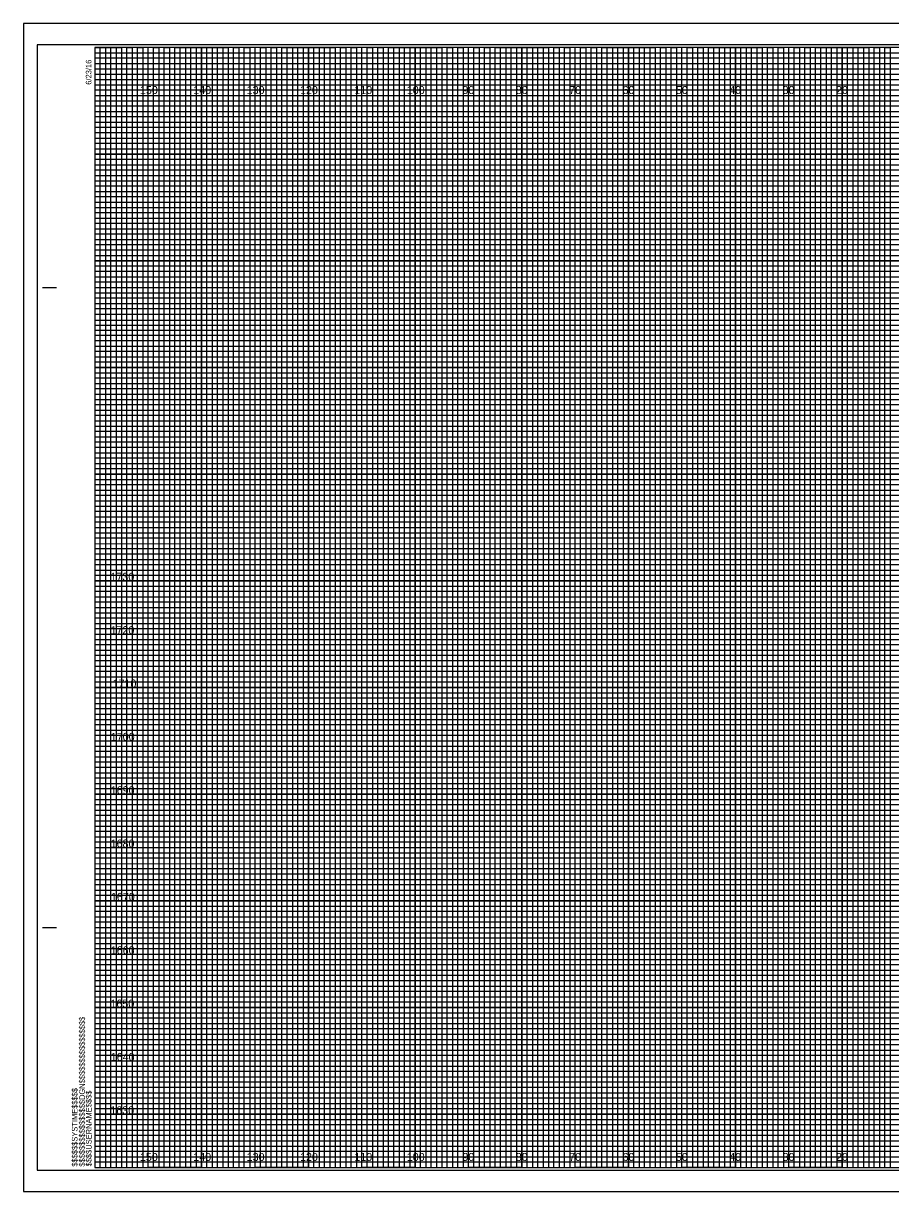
# Model space of a CAD drawing. Extents: x -13 to 323, y -5 to 6154.
# Drawn here: x -13.4 to 149.1, y 1315.5 to 1534.5 of the extents above; entities that cross this region are included whole.
import ezdxf

# ---------------------------------------------------------------- set-up
doc = ezdxf.new("R2010")
doc.units = 0
for name, color, linetype in [('Prop Retaining Wall', 7, 'Continuous'), ('Prop XS Alignment Label', 7, 'Continuous'), ('Prop XS DDE', 7, 'Continuous'), ('Prop XS DDE Elevations', 7, 'Continuous'), ('Prop XS DDE Slope Text', 7, 'Continuous'), ('Prop XS Earthwork Shape', 7, 'Continuous'), ('Prop XS Elevation Labels', 7, 'Continuous'), ('Prop XS Station Labels', 7, 'Continuous'), ('Raster_Level_0', 7, 'Continuous'), ('Scratch_Level_3', 7, 'Continuous'), ('Sheet Cutting Line CELL', 7, 'Continuous')]:
    doc.layers.add(name, color=color, linetype=linetype)

msp = doc.modelspace()

# ---------------------------------------------------------------- linework, layer by layer
at = {"layer": 'Prop Retaining Wall'}
for p, q in [((0, 1529), (260, 1529)), ((260, 1527.98), (0, 1527.98)), ((0, 1527.98), (0, 1527)), ((0, 1527), (260, 1527)), ((260, 1525.89), (0, 1525.89)), ((0, 1525.89), (0, 1524)), ((0, 1524), (320, 1524))]:
    msp.add_line(p, q, dxfattribs=at)
for points in [[(0, 1523), (270, 1523), (320, 1523), (320, 1522), (0, 1522)], [(0, 1521), (320, 1521), (320, 1519), (0, 1519)], [(0, 1518), (320, 1518), (320, 1517), (0, 1516.98)], [(0, 1516), (320, 1516), (320, 1514), (0, 1514)], [(0, 1513), (320, 1513), (320, 1512), (0, 1512)], [(0, 1511), (320, 1511), (320, 1509), (0, 1509)], [(0, 1508), (320, 1508), (320, 1507), (0, 1507)], [(0, 1506), (320, 1506), (320, 1504), (0, 1504)], [(0, 1503), (320, 1503), (320, 1502), (0, 1502)], [(0, 1501), (320, 1501), (320, 1499), (0, 1499)], [(0, 1498), (320, 1498), (320, 1497), (0, 1497)], [(0, 1496), (320, 1496), (320, 1493.95), (320, 1493), (320, 1492), (0, 1492)], [(0, 1494), (320, 1494), (320, 1493), (0, 1493)], [(0, 1491), (320, 1491), (320, 1489), (0, 1489.03)], [(0, 1489.03), (320, 1489), (320, 1488), (0, 1488)], [(0, 1487), (320, 1487), (320, 1486), (0, 1486)], [(0, 1484), (320, 1484), (320, 1483), (0, 1483)], [(0, 1482), (320, 1482), (320, 1481), (0, 1481)], [(-0.07, 1478.89), (320, 1478.89), (320, 1477.88), (-0.07, 1477.88)], [(0, 1477), (320, 1477), (320, 1476), (0, 1476)], [(0, 1474), (320, 1474), (320, 1473), (0, 1473)], [(0, 1472), (320, 1472), (320, 1471), (0, 1471)], [(0, 1469), (320, 1469), (320, 1468), (0, 1468)], [(0, 1467), (320, 1467), (320, 1466), (0, 1466)], [(0, 1464), (320, 1464), (320, 1463), (0, 1463)], [(0, 1462), (320, 1462), (320, 1461), (0, 1461)], [(0, 1459), (320, 1459), (319.99, 1457.98), (0, 1458)], [(0, 1457), (320, 1457), (320, 1456), (0, 1456)], [(0, 1454), (320, 1454), (320, 1453), (0, 1453)], [(0, 1452), (320, 1452), (320, 1451), (0, 1451)], [(0, 1449), (320, 1449), (320, 1448), (0, 1448)], [(0, 1447), (320, 1447), (320, 1446), (0, 1446)], [(0, 1444), (320, 1444), (320, 1443), (0, 1443)], [(0, 1442), (320, 1442), (320, 1441), (0, 1441)], [(0, 1439), (320, 1439), (320, 1438), (0, 1438)], [(0, 1436.99), (320.07, 1436.91), (320, 1436), (0, 1436)], [(0, 1434), (320, 1434), (320, 1433), (0, 1433)], [(0, 1432), (320, 1432), (320, 1431), (0, 1431)], [(0, 1429), (320, 1429), (320, 1428), (0, 1428)], [(0, 1427), (320, 1427), (320, 1426), (0, 1426)], [(0, 1424), (320, 1424), (320, 1423), (0, 1423)], [(0, 1422), (320, 1422), (320, 1421), (0, 1421)], [(0, 1419), (320, 1419), (320, 1418), (0, 1418)], [(0, 1417), (320, 1417), (320, 1416), (0, 1416)], [(0, 1414), (320, 1414), (320, 1413), (0, 1413)], [(0, 1412), (320, 1412), (320, 1411), (0, 1411)], [(0, 1409), (320, 1409), (320, 1408), (0, 1408)], [(0, 1407), (320, 1407), (320, 1406), (0, 1406)], [(0, 1404), (320, 1404), (320, 1403), (0, 1403)], [(0, 1402), (320, 1402), (320, 1401), (0, 1401)], [(0, 1399), (320, 1399), (319.99, 1397.98), (0, 1398)], [(0, 1397), (320, 1397), (320, 1396), (0, 1396)], [(0, 1394), (320, 1394), (320, 1393), (0, 1393)], [(0, 1392), (320, 1392), (320, 1391), (0, 1391)], [(0, 1389), (320, 1389), (320, 1388), (0, 1388)], [(0, 1387), (320, 1387), (320, 1386), (0, 1386)], [(0, 1384), (320, 1384), (320, 1383), (0, 1383)], [(0, 1382), (320, 1382), (320, 1381), (0, 1381)], [(0, 1379), (320, 1379), (320, 1378), (0, 1378)], [(0, 1376.99), (320.07, 1376.91), (320, 1376), (0, 1376)], [(0, 1374), (320, 1374), (320, 1373), (0, 1373)], [(0, 1372), (320, 1372), (320, 1371), (0, 1371)], [(0, 1369), (320, 1369), (320, 1368), (0, 1368)], [(0, 1367), (320, 1367), (320, 1366), (0, 1366)], [(0, 1364), (320, 1364), (320, 1363), (0, 1363)], [(0, 1362), (320, 1362), (320, 1361), (0, 1361)], [(0, 1359), (320, 1359), (320, 1358), (0, 1358)], [(0, 1357), (320, 1357), (320, 1356), (0, 1356)], [(0, 1354), (320, 1354), (320, 1353), (0, 1353)], [(0, 1352), (320, 1352), (320, 1351), (0, 1351)], [(0, 1349), (320, 1349), (320, 1348), (0, 1348)], [(0, 1347), (320, 1347), (320, 1346), (0, 1346)], [(0, 1344), (320, 1344), (320, 1343), (0, 1343)], [(0, 1342), (320, 1342), (320, 1341), (0, 1341)], [(0, 1339), (320, 1339), (320, 1338), (0, 1338)], [(0, 1337), (320, 1337), (320, 1336), (0, 1336)], [(0, 1334), (320, 1334), (320, 1333), (0, 1333)], [(0, 1332), (320, 1332), (320, 1331), (0, 1331)], [(0, 1329), (320, 1329), (320, 1328), (0, 1328)], [(0, 1327), (320, 1327), (320, 1326), (0, 1326)], [(0, 1324), (320, 1324), (320, 1323), (0, 1323)], [(0, 1322), (320, 1322), (320, 1321), (0, 1321)]]:
    msp.add_lwpolyline(points, dxfattribs=at)
at = {"layer": 'Prop XS Alignment Label'}
for p, q in [((-9.8, 1485), (-7.3, 1485)), ((-9.7, 1485), (-7.2, 1485)), ((-9.8, 1365), (-7.3, 1365)), ((-9.7, 1365), (-7.2, 1365)), ((0, 1320), (0, 1320)), ((0, 1320), (0, 1320)), ((0, 1320), (0, 1320)), ((0, 1320), (0, 1320)), ((0, 1320), (0, 1320)), ((0, 1320), (0, 1320)), ((0, 1320), (0, 1320))]:
    msp.add_line(p, q, dxfattribs=at)
msp.add_lwpolyline([(320, 1530), (0, 1530), (0, 1320), (320, 1320)], close=True, dxfattribs=at)
at = {"layer": 'Prop XS DDE'}
msp.add_lwpolyline([(-13.4, 1315.5), (323.3, 1315.5), (323.3, 1534.5), (-13.4, 1534.5)], close=True, dxfattribs=at)
at = {"layer": 'Prop XS DDE Elevations'}
for p, q in [((10, 1320), (10, 1530)), ((20, 1320), (20, 1530)), ((30, 1320), (30, 1530)), ((40, 1320), (40, 1530)), ((50, 1320), (50, 1530)), ((60, 1320), (60, 1530)), ((70, 1320), (70, 1530)), ((80, 1320), (80, 1530)), ((90, 1320), (90, 1530)), ((100, 1320), (100, 1530)), ((110, 1320), (110, 1530)), ((120, 1320), (120, 1530)), ((130, 1320), (130, 1530)), ((140, 1320), (140, 1530)), ((0, 1520), (320, 1520)), ((0, 1510), (320, 1510)), ((0, 1500), (320, 1500)), ((0, 1490), (320, 1490)), ((0, 1480), (320, 1480)), ((0, 1470), (320, 1470)), ((0, 1460), (320, 1460)), ((0, 1450), (320, 1450)), ((0, 1440), (320, 1440)), ((0, 1430), (320, 1430)), ((0, 1420), (320, 1420)), ((0, 1410), (320, 1410)), ((0, 1400), (320, 1400)), ((0, 1390), (320, 1390)), ((0, 1380), (320, 1380)), ((0, 1370), (320, 1370)), ((0, 1360), (320, 1360)), ((0, 1350), (320, 1350)), ((0, 1340), (320, 1340)), ((0, 1330), (320, 1330))]:
    msp.add_line(p, q, dxfattribs=at)
at = {"layer": 'Prop XS DDE Slope Text'}
msp.add_lwpolyline([(-10.8, 1319.5), (322.4, 1319.5), (322.4, 1530.5), (-10.8, 1530.5)], close=True, dxfattribs=at)
at = {"layer": 'Prop XS Earthwork Shape'}
for p, q in [((10, 1530), (0, 1530)), ((10, 1320), (10, 1530)), ((30, 1530), (20, 1530)), ((20, 1530), (20, 1320)), ((30, 1320), (30, 1530)), ((50, 1530), (40, 1530)), ((40, 1530), (40, 1320)), ((50, 1320), (50, 1530)), ((70, 1530), (60, 1530)), ((60, 1530), (60, 1320)), ((70, 1320), (70, 1530)), ((90, 1530), (80, 1530)), ((80, 1530), (80, 1320)), ((90, 1320), (90, 1530)), ((110, 1530), (100, 1530)), ((100, 1530), (100, 1320)), ((110, 1320), (110, 1530)), ((130, 1530), (120, 1530)), ((120, 1530), (120, 1320)), ((130, 1320), (130, 1530)), ((150, 1530), (140, 1530)), ((140, 1530), (140, 1320)), ((20, 1320), (10, 1320)), ((40, 1320), (30, 1320)), ((60, 1320), (50, 1320)), ((80, 1320), (70, 1320)), ((100, 1320), (90, 1320)), ((120, 1320), (110, 1320)), ((140, 1320), (130, 1320))]:
    msp.add_line(p, q, dxfattribs=at)
for points in [[(0, 1520), (320, 1520), (320, 1510), (0, 1510)], [(0, 1500), (320, 1500), (320, 1490), (0, 1490)], [(0, 1480), (320, 1480), (320, 1470), (0, 1470)], [(0, 1460), (320, 1460), (320, 1450), (0, 1450)], [(0, 1440), (320, 1440), (320, 1430), (0, 1430)], [(0, 1420), (320, 1420), (320, 1410), (0, 1410)], [(0, 1400), (320, 1400), (320, 1390), (0, 1390)], [(0, 1380), (320, 1380), (320, 1370), (0, 1370)], [(0, 1360), (320, 1360), (320, 1350), (0, 1350)], [(0, 1340), (320, 1340), (320, 1330), (0, 1330)]]:
    msp.add_lwpolyline(points, dxfattribs=at)
at = {"layer": 'Prop XS Elevation Labels'}
for points in [[(0, 1320), (1, 1320), (1, 1530), (2, 1530), (2, 1320)], [(2, 1320), (3, 1320), (3, 1530), (4, 1530), (4, 1320)], [(5, 1320), (6, 1320), (6, 1530), (7, 1530), (7, 1320)], [(7, 1320), (8, 1320), (8, 1530), (9, 1530), (9, 1320)], [(10, 1320), (11, 1320), (11, 1530), (12, 1530), (12, 1320)], [(12, 1320), (13, 1320), (13, 1530), (14, 1530), (14, 1320)], [(15, 1320), (16, 1320), (16, 1530), (17, 1530), (17, 1320)], [(17, 1320), (18, 1320), (18, 1530), (19, 1530), (19, 1320)], [(20, 1320), (21, 1320), (21, 1530), (22, 1530), (22, 1320)], [(22, 1320), (23, 1320), (23, 1530), (24, 1530), (24, 1320)], [(25, 1320), (26, 1320), (26, 1530), (27, 1530), (27, 1320)], [(27, 1320), (28, 1320), (28, 1530), (29, 1530), (29, 1320)], [(30, 1320), (31, 1320), (31, 1530), (32, 1530), (32, 1320)], [(32, 1320), (33, 1320), (33, 1530), (34, 1530), (34, 1320)], [(35, 1320), (36, 1320), (36, 1530), (37, 1530), (37, 1320)], [(37, 1320), (38, 1320), (38, 1530), (39, 1530), (39, 1320)], [(40, 1320), (41, 1320), (41, 1530), (42, 1530), (42, 1320)], [(42, 1320), (43, 1320), (43, 1530), (44, 1530), (44, 1320)], [(45, 1320), (46, 1320), (46, 1530), (47, 1530), (47, 1320)], [(47, 1320), (48, 1320), (48, 1530), (49, 1530), (49, 1320)], [(50, 1320), (51, 1320), (51, 1530), (52, 1530), (52, 1320)], [(52, 1320), (53, 1320), (53, 1530), (54, 1530), (54, 1320)], [(55, 1320), (56, 1320), (56, 1530), (57, 1530), (57, 1320)], [(57, 1320), (58, 1320), (58, 1530), (59, 1530), (59, 1320)], [(60, 1320), (61, 1320), (61, 1530), (62, 1530), (62, 1320)], [(62, 1320), (63, 1320), (63, 1530), (64, 1530), (64, 1320)], [(65, 1320), (66, 1320), (66, 1530), (67, 1530), (67, 1320)], [(67, 1320), (68, 1320), (68, 1530), (69, 1530), (69, 1320)], [(70, 1320), (71, 1320), (71, 1530), (72, 1530), (72, 1320)], [(72, 1320), (73, 1320), (73, 1530), (74, 1530), (74, 1320)], [(75, 1320), (76, 1320), (76, 1530), (77, 1530), (77, 1320)], [(77, 1320), (78, 1320), (78, 1530), (79, 1530), (79, 1320)], [(80, 1320), (81, 1320), (81, 1530), (82, 1530), (82, 1320)], [(82, 1320), (83, 1320), (83, 1530), (84, 1530), (84, 1320)], [(85, 1320), (86, 1320), (86, 1530), (87, 1530), (87, 1320)], [(87, 1320), (88, 1320), (88, 1530), (89, 1530), (89, 1320)], [(90, 1320), (91, 1320), (91, 1530), (92, 1530), (92, 1320)], [(92, 1320), (93, 1320), (93, 1530), (94, 1530), (94, 1320)], [(95, 1320), (96, 1320), (96, 1530), (97, 1530), (97, 1320)], [(97, 1320), (98, 1320), (98, 1530), (99, 1530), (99, 1320)], [(100, 1320), (101, 1320), (101, 1530), (102, 1530), (102, 1320)], [(102, 1320), (103, 1320), (103, 1530), (104, 1530), (104, 1320)], [(105, 1320), (106, 1320), (106, 1530), (107, 1530), (107, 1320)], [(107, 1320), (108, 1320), (108, 1530), (109, 1530), (109, 1320)], [(110, 1320), (111, 1320), (111, 1530), (112, 1530), (112, 1320)], [(112, 1320), (113, 1320), (113, 1530), (114, 1530), (114, 1320)], [(115, 1320), (116, 1320), (116, 1530), (117, 1530), (117, 1320)], [(117, 1320), (118, 1320), (118, 1530), (119, 1530), (119, 1320)], [(120, 1320), (121, 1320), (121, 1530), (122, 1530), (122, 1320)], [(122, 1320), (123, 1320), (123, 1530), (124, 1530), (124, 1320)], [(125, 1320), (126, 1320), (126, 1530), (127, 1530), (127, 1320)], [(127, 1320), (128, 1320), (128, 1530), (129, 1530), (129, 1320)], [(130, 1320), (131, 1320), (131, 1530), (132, 1530), (132, 1320)], [(132, 1320), (133, 1320), (133, 1530), (134, 1530), (134, 1320)], [(135, 1320), (136, 1320), (136, 1530), (137, 1530), (137, 1320)], [(137, 1320), (138, 1320), (138, 1530), (139, 1530), (139, 1320)], [(140, 1320), (141, 1320), (141, 1530), (142, 1530), (142, 1320)], [(142, 1320), (143, 1320), (143, 1530), (144, 1530), (144, 1320)], [(145, 1320), (146, 1320), (146, 1530), (147, 1530), (147, 1320)], [(147, 1320), (148, 1320), (148, 1530), (149, 1530), (149, 1320)]]:
    msp.add_lwpolyline(points, dxfattribs=at)
at = {"layer": 'Prop XS Station Labels'}
for points in [[(0, 1530), (5, 1530), (5, 1320), (15, 1320), (15, 1530), (25, 1530), (25, 1320), (35, 1320), (35, 1530), (45, 1530), (45, 1320), (55, 1320), (55, 1530), (65, 1530), (65, 1320), (75, 1320), (75, 1530), (85, 1530), (85, 1320), (95, 1320), (95, 1530), (105, 1530), (105, 1320), (115, 1320), (115, 1530), (125, 1530), (125, 1320), (135, 1320), (135, 1530), (145, 1530), (145, 1320), (155, 1320)], [(0, 1525), (275, 1525)], [(0, 1505), (320, 1505), (320, 1515), (0, 1515)], [(0, 1485), (320, 1485), (320, 1495), (0, 1495)], [(0, 1465), (320, 1465), (320, 1475), (0, 1475)], [(0, 1445), (320, 1445), (320, 1455), (0, 1455)], [(0, 1425), (320, 1425), (320, 1435), (0, 1435)], [(0, 1405), (320, 1405), (320, 1415), (0, 1415)], [(0, 1385), (320, 1385), (320, 1395), (0, 1395)], [(0, 1365), (320, 1365), (320, 1375), (0, 1375)], [(0, 1345), (320, 1345), (320, 1355), (0, 1355)], [(0, 1325), (320, 1325), (320, 1335), (0, 1335)]]:
    msp.add_lwpolyline(points, dxfattribs=at)
at = {"layer": 'Sheet Cutting Line CELL'}
for p, q in [((323.3, 1534.5), (-13.4, 1534.5)), ((-13.4, 1534.5), (-13.4, 1315.5)), ((-13.4, 1315.5), (323.3, 1315.5))]:
    msp.add_line(p, q, dxfattribs=at)

# ---------------------------------------------------------------- texts
at = {"layer": 'Prop XS Alignment Label'}
for s, p in [('6/23/16', (-0.65, 1523)), ('$$$$$$$$$$$$$$$$DGN$$$$$$$$$$$$$$$$', (-1.88, 1320.18)), ('$$$$$$SYSTIME$$$$$', (-3.26, 1320.18)), ('$$$$USERNAME$$$$', (-0.62, 1320.23))]:
    msp.add_text(s, height=1.05, rotation=90, dxfattribs=at).set_placement(p)
at = {"layer": 'Raster_Level_0'}
for s, p in [('150', (8.44, 1521.25)), ('140', (18.44, 1521.25)), ('130', (28.44, 1521.25)), ('120', (38.44, 1521.25)), ('110', (48.62, 1521.25)), ('100', (58.44, 1521.25)), ('90', (68.86, 1521.25)), ('80', (78.86, 1521.25)), ('70', (88.86, 1521.25)), ('60', (98.86, 1521.25)), ('50', (108.86, 1521.25)), ('40', (118.86, 1521.25)), ('30', (128.86, 1521.25)), ('20', (138.86, 1521.25)), ('150', (8.44, 1321.25)), ('140', (18.44, 1321.25)), ('130', (28.44, 1321.25)), ('120', (38.44, 1321.25)), ('110', (48.62, 1321.25)), ('100', (58.44, 1321.25)), ('90', (68.86, 1321.25)), ('80', (78.86, 1321.25)), ('70', (88.86, 1321.25)), ('60', (98.86, 1321.25)), ('50', (108.86, 1321.25)), ('40', (118.86, 1321.25)), ('30', (128.86, 1321.25)), ('20', (138.86, 1321.25))]:
    msp.add_text(s, height=1.5, dxfattribs=at).set_placement(p)
at = {"layer": 'Scratch_Level_3'}
for s, p in [('1730', (2.92, 1430)), ('1720', (2.93, 1420)), ('1710', (3.31, 1410)), ('1700', (2.98, 1400)), ('1690', (2.97, 1390)), ('1680', (2.95, 1380)), ('1670', (3, 1370)), ('1660', (2.97, 1360)), ('1650', (2.92, 1350)), ('1640', (2.97, 1340)), ('1630', (2.89, 1330))]:
    msp.add_text(s, height=1.5, dxfattribs=at).set_placement(p)

doc.saveas('drawing.dxf')
